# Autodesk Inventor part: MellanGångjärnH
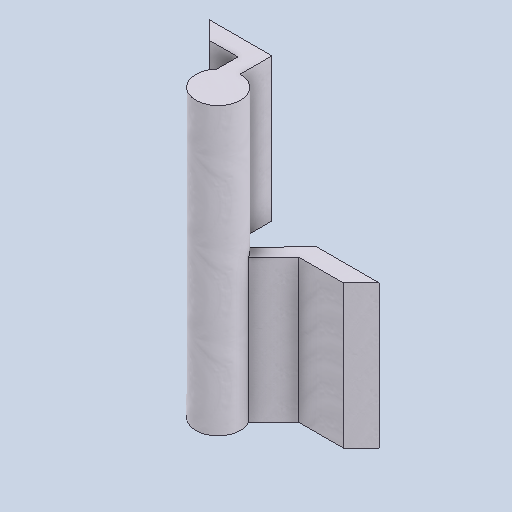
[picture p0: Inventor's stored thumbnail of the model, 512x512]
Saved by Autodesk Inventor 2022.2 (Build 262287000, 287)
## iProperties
Created: 2019-06
Part Number: MellanGångjärnH
Material: Aluminum 6061, Welded
Document SubType Name: Modeling
Designer: cl
Density: 2.7 g/cm^3
Appearance: Weld - Aluminum
Author: cl
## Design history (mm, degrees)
sketch "Sketch1"
  geometry: L1 (0, 0)-(35, 0); L2 (0, 0)-(10, 10); L3 (10, 10)-(35, 10); L4 (35, 10)-(48.901, 24.182); L5 (35, 0)-(53.9, 19.282); L6 (48.901, 24.182)-(85.631, -11.821); A1 r 12.5 centre (59.801, 30.302) between (53.9, 19.282) and (48.901, 24.182)
  constraints: 12 end point, 2 horizontal, 2 point on circle, 1 centre point, 1 parallel, 1 perpendicular, 1 point on line
  dimensions: "d4" = 35 distance of L1.start L1.end; "d6" = 45 deg angle of L1 L2; "d7" = 10 distance between parallel lines of L1 L3; "d8" = 25 distance of L2.end L3.end; "d9" = 27 distance of L1.end L5.end; "d10" = 7 distance between parallel lines of L5 L4; "d11" = 25 diameter of A1
extrude "Extrusion1" new body sketch "Sketch1" distance "d12" = 80; taper "d13" = 0 deg
sketch "Sketch2"
  geometry: L1 (-48.901, -24.182)-(-35, -10) reference; L2 (-35, -10)-(-10, -10) reference; L3 (-10, -10)-(0, 0) reference; L4 (0, 0)-(-35, 0) reference; L5 (-35, 0)-(-53.9, -19.282) reference; L6 (-60, -17.803)-(-60, 0); L7 (-60, 0)-(-95, 0); L8 (-95, 0)-(-85, -10); L9 (-95, 0)-(-80.858, 0); L10 (-85, -10)-(-69, -10); L11 (-69, -10)-(-69, -21.839); L12 (0, 0)-(-35, 0) reference; A1 r 12.5 centre (-59.801, -30.302) between (-69, -21.839) and (-60, -17.803); A2 r 12.5 centre (-59.801, -30.302) between (-53.9, -19.282) and (-48.901, -24.182) reference; A3 r 12.5 centre (-59.801, -30.302) between (-53.9, -19.282) and (-48.901, -24.182) reference; A4 r 12.5 centre (-59.801, -30.302) between (-53.9, -19.282) and (-48.901, -24.182) reference
  constraints: 12 end point, 3 horizontal, 2 point on circle, 2 vertical, 1 centre point, 1 coincident, 1 collinear, 1 equal length
  dimensions: "d14" = 25 distance of L4.end L6.end; "d15" = 35 distance of L6.end L7.end; "d16" = 45 deg angle of L8 L9; "d17" = 10 distance between parallel lines of L7 L10; "d22" = 25 diameter of A1; "d23" = 9 distance between parallel lines of L11 L6
extrude "Extrusion2" join sketch "Sketch2" distance "d24" = 80; taper "d25" = 0 deg
body "Solid1"
node "Projected Loop1"
node "Projected Loop2"
